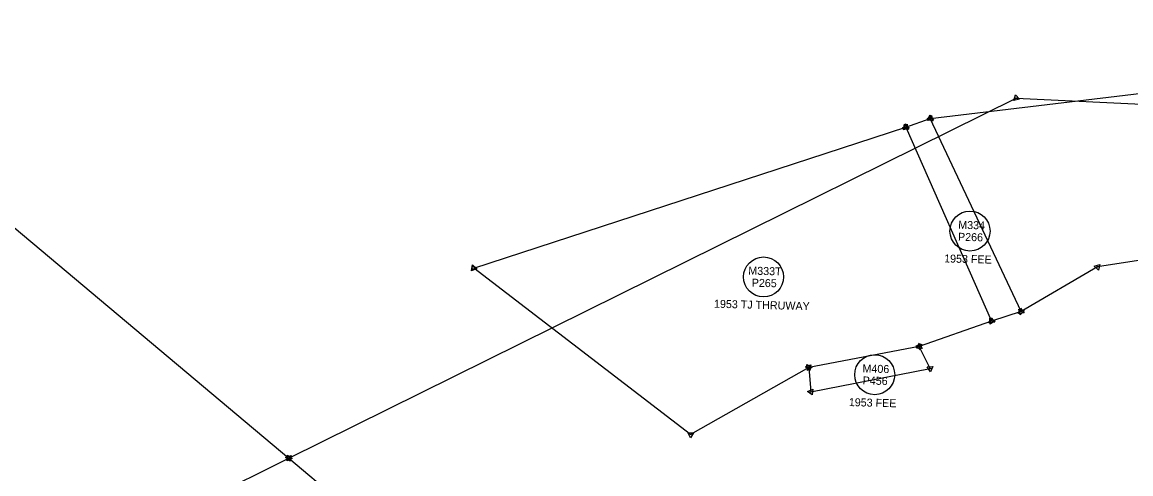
# Model space of a CAD drawing. Extents: x 325018 to 414989, y 1517547 to 1550415.
# Drawn here: x 363499 to 364226, y 1524267 to 1524563 of the extents above; entities that cross this region are included whole.
import ezdxf

# ---------------------------------------------------------------- set-up
doc = ezdxf.new("R2010")
doc.units = 0
for name, color, linetype in [('Level 56', 7, 'Continuous'), ('MHB', 7, 'Continuous'), ('MRBL1', 7, 'Continuous'), ('MRBL2', 7, 'Continuous')]:
    doc.layers.add(name, color=color, linetype=linetype)

msp = doc.modelspace()

# ---------------------------------------------------------------- linework, layer by layer
at = {"layer": 'Level 56'}
for centre in [(364120.49, 1524426.26), (363985.06, 1524396.11), (364057.97, 1524331.91)]:
    msp.add_circle(centre, 13.12, dxfattribs=at)
at = {"layer": 'MHB'}
for p, q in [((364094.47, 1524500.15), (364618.27, 1524563.46)), ((364078.35, 1524494.39), (364094.47, 1524500.15)), ((364153.96, 1524373.38), (364094.47, 1524500.15)), ((363794.94, 1524401.92), (364078.35, 1524494.39)), ((364078.35, 1524494.39), (364134.7, 1524367.19)), ((364776.1, 1524492.9), (364204.15, 1524402.72)), ((363937.22, 1524292.75), (363794.94, 1524401.92)), ((364204.15, 1524402.72), (364153.96, 1524373.38)), ((364134.7, 1524367.19), (364087.24, 1524350.36)), ((364153.96, 1524373.38), (364134.7, 1524367.19)), ((364087.24, 1524350.36), (364014.74, 1524336.75)), ((364094.35, 1524336.02), (364087.24, 1524350.36)), ((364014.74, 1524336.75), (363937.22, 1524292.75)), ((364014.74, 1524336.75), (364016.03, 1524320.65)), ((364016.03, 1524320.65), (364094.35, 1524336.02))]:
    msp.add_line(p, q, dxfattribs=at)
for points in [[(364092.31, 1524499.87), (364095.31, 1524502.16)], [(364095.8, 1524498.42), (364092.31, 1524499.87)], [(364092.5, 1524499.23), (364094.66, 1524502.33)], [(364096.27, 1524498.91), (364092.5, 1524499.23)], [(364092.73, 1524498.84), (364094.21, 1524502.31)], [(364096.48, 1524499.29), (364092.73, 1524498.84)], [(364094.21, 1524502.31), (364096.48, 1524499.29)], [(364094.66, 1524502.33), (364096.27, 1524498.91)], [(364095.31, 1524502.16), (364095.8, 1524498.42)], [(364076.18, 1524494.16), (364079.24, 1524496.38)], [(364079.63, 1524492.63), (364076.18, 1524494.16)], [(364076.36, 1524493.51), (364078.59, 1524496.57)], [(364080.12, 1524493.11), (364076.36, 1524493.51)], [(364076.94, 1524492.73), (364077.62, 1524496.45)], [(364080.5, 1524494), (364076.94, 1524492.73)], [(364077.62, 1524496.45), (364080.5, 1524494)], [(364078.59, 1524496.57), (364080.12, 1524493.11)], [(364079.24, 1524496.38), (364079.63, 1524492.63)], [(363793.48, 1524400.29), (363794.27, 1524403.99)], [(363793.62, 1524400.19), (363794.11, 1524403.94)], [(363794.11, 1524403.94), (363797.11, 1524401.64)], [(363794.27, 1524403.99), (363797.08, 1524401.47)], [(364202, 1524403.12), (364205.56, 1524404.39)], [(364205.56, 1524404.39), (364204.88, 1524400.67)], [(363797.08, 1524401.47), (363793.48, 1524400.29)], [(363797.11, 1524401.64), (363793.62, 1524400.19)], [(364204.88, 1524400.67), (364202, 1524403.12)], [(364152.2, 1524372.09), (364153.71, 1524375.55)], [(364153.31, 1524371.3), (364152.48, 1524374.99)], [(364152.48, 1524374.99), (364156.09, 1524373.86)], [(364153.71, 1524375.55), (364155.95, 1524372.51)], [(364132.95, 1524365.89), (364134.45, 1524369.36)], [(364133.81, 1524365.2), (364133.43, 1524368.96)], [(364133.43, 1524368.96), (364136.88, 1524367.41)], [(364136.88, 1524367.41), (364133.81, 1524365.2)], [(364134.45, 1524369.36), (364136.7, 1524366.33)], [(364155.95, 1524372.51), (364152.2, 1524372.09)], [(364156.09, 1524373.86), (364153.31, 1524371.3)], [(364136.7, 1524366.33), (364132.95, 1524365.89)], [(364085.29, 1524349.39), (364087.38, 1524352.54)], [(364087.38, 1524352.54), (364089.06, 1524349.15)], [(364085.13, 1524350.92), (364088.78, 1524351.91)], [(364087.81, 1524348.26), (364085.13, 1524350.92)], [(364089.06, 1524349.15), (364085.29, 1524349.39)], [(364088.78, 1524351.91), (364087.81, 1524348.26)], [(364012.59, 1524337.13), (364016.14, 1524338.43)], [(364013.5, 1524338.55), (364016.91, 1524336.92)], [(364013.8, 1524334.78), (364013.5, 1524338.55)], [(364016.14, 1524338.43), (364015.49, 1524334.71)], [(364015.49, 1524334.71), (364012.59, 1524337.13)], [(364016.91, 1524336.92), (364013.8, 1524334.78)], [(364092.39, 1524336.99), (364096.16, 1524337.23)], [(364094.49, 1524333.85), (364092.39, 1524336.99)], [(364096.16, 1524337.23), (364094.49, 1524333.85)], [(364013.86, 1524320.92), (364017.34, 1524322.38)], [(364016.87, 1524318.63), (364013.86, 1524320.92)], [(364017.34, 1524322.38), (364016.87, 1524318.63)], [(363937.07, 1524290.57), (363935.41, 1524293.97)], [(363935.41, 1524293.97), (363939.18, 1524293.71)], [(363939.18, 1524293.71), (363937.07, 1524290.57)]]:
    msp.add_lwpolyline(points, dxfattribs=at)
for centre, radius in [((364094.48, 1524500.15), 1.09), ((364094.47, 1524500.15), 1.09), ((364094.47, 1524500.15), 0.227), ((364078.36, 1524494.4), 1.09), ((364078.35, 1524494.4), 1.09), ((364078.35, 1524494.39), 0.227), ((363794.94, 1524401.92), 1.09), ((363794.94, 1524401.92), 1.09), ((364204.15, 1524402.72), 0.227), ((364134.7, 1524367.19), 0.227), ((364134.7, 1524367.19), 0.227), ((364153.96, 1524373.38), 0.227), ((364153.96, 1524373.38), 0.227), ((364087.24, 1524350.36), 1.09), ((364087.24, 1524350.36), 0.227), ((364014.74, 1524336.75), 1.09), ((364014.74, 1524336.75), 0.227), ((364094.35, 1524336.02), 0.227), ((364016.03, 1524320.65), 0.227), ((363937.22, 1524292.75), 0.227)]:
    msp.add_circle(centre, radius, dxfattribs=at)
at = {"layer": 'MRBL1'}
for p, q in [((363673.76, 1524277.12), (364150.79, 1524513.55)), ((364150.79, 1524513.55), (365471, 1524450.93)), ((362781.13, 1523834.71), (363673.76, 1524277.12))]:
    msp.add_line(p, q, dxfattribs=at)
for points in [[(364149.16, 1524512.1), (364150.34, 1524515.69)], [(364152.86, 1524512.87), (364149.16, 1524512.1)], [(364150.34, 1524515.69), (364152.86, 1524512.87)], [(363672.55, 1524275.3), (363672.79, 1524279.07)], [(363675.93, 1524276.98), (363672.55, 1524275.3)], [(363672.79, 1524279.07), (363675.93, 1524276.98)]]:
    msp.add_lwpolyline(points, dxfattribs=at)
for centre in [(364150.79, 1524513.55), (363673.76, 1524277.12)]:
    msp.add_circle(centre, 0.227, dxfattribs=at)
at = {"layer": 'MRBL2'}
for p, q in [((363395.94, 1524510.39), (363673.76, 1524277.12)), ((363673.76, 1524277.12), (363809.01, 1524163.56))]:
    msp.add_line(p, q, dxfattribs=at)
for points in [[(363671.61, 1524277.5), (363675.16, 1524278.79)], [(363674.5, 1524275.07), (363671.61, 1524277.5)], [(363675.16, 1524278.79), (363674.5, 1524275.07)]]:
    msp.add_lwpolyline(points, dxfattribs=at)
msp.add_circle((363673.76, 1524277.12), 0.227, dxfattribs=at)

# ---------------------------------------------------------------- texts
at = {"layer": 'Level 56'}
for s, height, p in [('M334', 5.249, (364112.73, 1524427.78)), ('P266', 5.249, (364112.58, 1524419.9)), ('1953 FEE', 5.249, (364103.47, 1524405.68)), ('M333T', 5.249, (363975.02, 1524397.68)), ('P265', 5.249, (363977.27, 1524389.75)), ('1953 TJ THRUWAY', 5.2493, (363952.52, 1524375.93)), ('M406', 5.249, (364049.92, 1524333.43)), ('P456', 5.249, (364050.03, 1524325.55)), ('1953 FEE', 5.249, (364040.95, 1524311.33))]:
    msp.add_text(s, height=height, rotation=358.51411, dxfattribs=at).set_placement(p)

doc.saveas('drawing.dxf')
